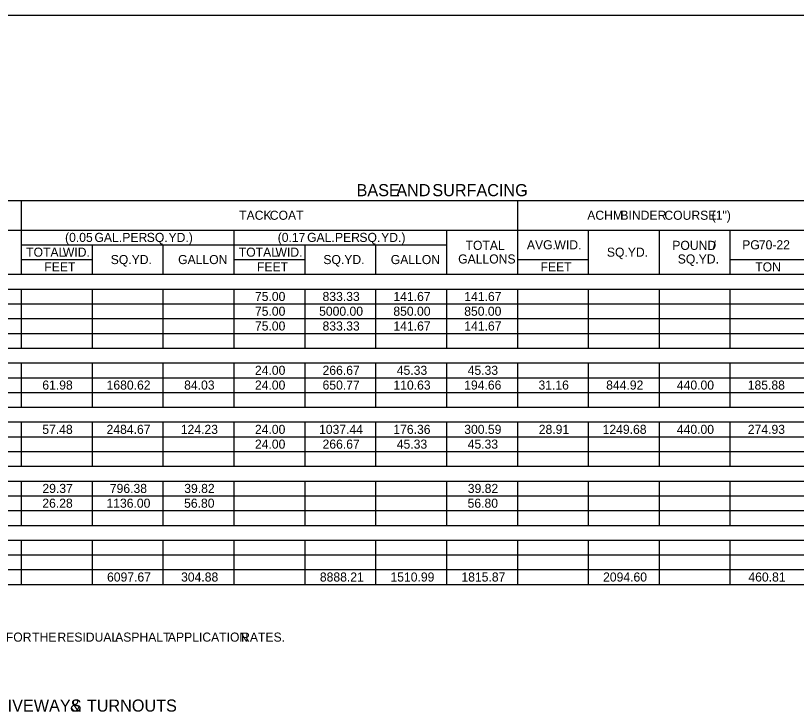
# Model space of a CAD drawing. Extents: x 3289 to 10164, y -1238 to -188.
# Drawn here: x 6334 to 6849, y -648 to -188 of the extents above; entities that cross this region are included whole.
import ezdxf

# ---------------------------------------------------------------- set-up
doc = ezdxf.new("R2010")
doc.units = 0
for name, color, linetype in [('Default', 7, 'Continuous'), ('DSN_DRFT_Named-Boundary', 7, 'Continuous'), ('DSN_QNTY_Annotation', 7, 'Continuous')]:
    doc.layers.add(name, color=color, linetype=linetype)

msp = doc.modelspace()

# ---------------------------------------------------------------- linework, layer by layer
at = {"layer": 'DSN_DRFT_Named-Boundary'}
msp.add_lwpolyline([(5913.57, -1237.74), (7538.57, -1237.74), (7538.57, -187.74), (5913.57, -187.74)], close=True, dxfattribs=at)
at = {"layer": 'DSN_QNTY_Annotation'}
for p, q in [((5941.78, -309.81), (7279.48, -309.81)), ((6337.63, -358.56), (6337.63, -309.81)), ((6665.23, -358.56), (6665.23, -309.81)), ((6244.03, -329.31), (7279.48, -329.31)), ((6478.03, -358.56), (6478.03, -329.31)), ((6618.43, -358.56), (6618.43, -329.31)), ((6712.03, -358.56), (6712.03, -329.31)), ((6758.83, -358.56), (6758.83, -329.31)), ((6805.63, -358.56), (6805.63, -329.31)), ((6337.63, -339.06), (6618.43, -339.06)), ((6384.43, -358.56), (6384.43, -339.06)), ((6431.23, -358.56), (6431.23, -339.06)), ((6524.83, -358.56), (6524.83, -339.06)), ((6571.63, -358.56), (6571.63, -339.06)), ((6337.63, -348.81), (6384.43, -348.81)), ((6384.43, -358.56), (6384.43, -348.81)), ((6478.03, -348.81), (6524.83, -348.81)), ((6524.83, -358.56), (6524.83, -348.81)), ((6665.23, -348.81), (6712.03, -348.81)), ((6712.03, -358.56), (6712.03, -348.81)), ((6805.63, -348.81), (6899.23, -348.81)), ((5941.78, -358.56), (7279.48, -358.56)), ((6244.03, -358.56), (6384.43, -358.56)), ((6384.43, -358.56), (6524.83, -358.56)), ((6524.83, -358.56), (6571.63, -358.56)), ((6571.63, -358.56), (6712.03, -358.56)), ((6712.03, -358.56), (6899.23, -358.56)), ((5941.78, -368.31), (7279.48, -368.31)), ((6337.63, -407.31), (6337.63, -368.31)), ((6337.63, -407.31), (6337.63, -368.31)), ((6384.43, -407.31), (6384.43, -368.31)), ((6384.43, -407.31), (6384.43, -368.31)), ((6431.23, -407.31), (6431.23, -368.31)), ((6431.23, -407.31), (6431.23, -368.31)), ((6478.03, -407.31), (6478.03, -368.31)), ((6478.03, -407.31), (6478.03, -368.31)), ((6524.83, -407.31), (6524.83, -368.31)), ((6524.83, -407.31), (6524.83, -368.31)), ((6571.63, -407.31), (6571.63, -368.31)), ((6571.63, -407.31), (6571.63, -368.31)), ((6618.43, -407.31), (6618.43, -368.31)), ((6618.43, -407.31), (6618.43, -368.31)), ((6665.23, -407.31), (6665.23, -368.31)), ((6665.23, -407.31), (6665.23, -368.31)), ((6712.03, -407.31), (6712.03, -368.31)), ((6712.03, -407.31), (6712.03, -368.31)), ((6758.83, -407.31), (6758.83, -368.31)), ((6758.83, -407.31), (6758.83, -368.31)), ((6805.63, -407.31), (6805.63, -368.31)), ((6805.63, -407.31), (6805.63, -368.31)), ((5941.78, -378.06), (7279.48, -378.06)), ((5941.78, -387.81), (7279.48, -387.81)), ((5941.78, -397.56), (7279.48, -397.56)), ((5941.78, -407.31), (6384.43, -407.31)), ((5941.78, -407.31), (7279.48, -407.31)), ((6384.43, -407.31), (6478.03, -407.31)), ((6478.03, -407.31), (6524.83, -407.31)), ((6524.83, -407.31), (6665.23, -407.31)), ((6665.23, -407.31), (7086.43, -407.31)), ((5941.78, -417.06), (7279.48, -417.06)), ((6337.63, -446.31), (6337.63, -417.06)), ((6337.63, -446.31), (6337.63, -417.06)), ((6384.43, -446.31), (6384.43, -417.06)), ((6384.43, -446.31), (6384.43, -417.06)), ((6431.23, -446.31), (6431.23, -417.06)), ((6431.23, -446.31), (6431.23, -417.06)), ((6478.03, -446.31), (6478.03, -417.06)), ((6478.03, -446.31), (6478.03, -417.06)), ((6524.83, -446.31), (6524.83, -417.06)), ((6524.83, -446.31), (6524.83, -417.06)), ((6571.63, -446.31), (6571.63, -417.06)), ((6571.63, -446.31), (6571.63, -417.06)), ((6618.43, -446.31), (6618.43, -417.06)), ((6618.43, -446.31), (6618.43, -417.06)), ((6665.23, -446.31), (6665.23, -417.06)), ((6665.23, -446.31), (6665.23, -417.06)), ((6712.03, -446.31), (6712.03, -417.06)), ((6712.03, -446.31), (6712.03, -417.06)), ((6758.83, -446.31), (6758.83, -417.06)), ((6758.83, -446.31), (6758.83, -417.06)), ((6805.63, -446.31), (6805.63, -417.06)), ((6805.63, -446.31), (6805.63, -417.06)), ((5941.78, -426.81), (7279.48, -426.81)), ((5941.78, -436.56), (7279.48, -436.56)), ((5941.78, -446.31), (6384.43, -446.31)), ((5941.78, -446.31), (7279.48, -446.31)), ((6384.43, -446.31), (6478.03, -446.31)), ((6478.03, -446.31), (6524.83, -446.31)), ((6524.83, -446.31), (6665.23, -446.31)), ((6665.23, -446.31), (7086.43, -446.31)), ((5941.78, -456.06), (7279.48, -456.06)), ((6337.63, -485.31), (6337.63, -456.06)), ((6337.63, -485.31), (6337.63, -456.06)), ((6384.43, -485.31), (6384.43, -456.06)), ((6384.43, -485.31), (6384.43, -456.06)), ((6431.23, -485.31), (6431.23, -456.06)), ((6431.23, -485.31), (6431.23, -456.06)), ((6478.03, -485.31), (6478.03, -456.06)), ((6478.03, -485.31), (6478.03, -456.06)), ((6524.83, -485.31), (6524.83, -456.06)), ((6524.83, -485.31), (6524.83, -456.06)), ((6571.63, -485.31), (6571.63, -456.06)), ((6571.63, -485.31), (6571.63, -456.06)), ((6618.43, -485.31), (6618.43, -456.06)), ((6618.43, -485.31), (6618.43, -456.06)), ((6665.23, -485.31), (6665.23, -456.06)), ((6665.23, -485.31), (6665.23, -456.06)), ((6712.03, -485.31), (6712.03, -456.06)), ((6712.03, -485.31), (6712.03, -456.06)), ((6758.83, -485.31), (6758.83, -456.06)), ((6758.83, -485.31), (6758.83, -456.06)), ((6805.63, -485.31), (6805.63, -456.06)), ((6805.63, -485.31), (6805.63, -456.06)), ((5941.78, -465.81), (7279.48, -465.81)), ((5941.78, -475.56), (7279.48, -475.56)), ((5941.78, -485.31), (6384.43, -485.31)), ((5941.78, -485.31), (7279.48, -485.31)), ((6384.43, -485.31), (6478.03, -485.31)), ((6478.03, -485.31), (6524.83, -485.31)), ((6524.83, -485.31), (6665.23, -485.31)), ((6665.23, -485.31), (7086.43, -485.31)), ((5941.78, -495.06), (7279.48, -495.06)), ((6337.63, -524.31), (6337.63, -495.06)), ((6337.63, -524.31), (6337.63, -495.06)), ((6384.43, -524.31), (6384.43, -495.06)), ((6384.43, -524.31), (6384.43, -495.06)), ((6431.23, -524.31), (6431.23, -495.06)), ((6431.23, -524.31), (6431.23, -495.06)), ((6478.03, -524.31), (6478.03, -495.06)), ((6478.03, -524.31), (6478.03, -495.06)), ((6524.83, -524.31), (6524.83, -495.06)), ((6524.83, -524.31), (6524.83, -495.06)), ((6571.63, -524.31), (6571.63, -495.06)), ((6571.63, -524.31), (6571.63, -495.06)), ((6618.43, -524.31), (6618.43, -495.06)), ((6618.43, -524.31), (6618.43, -495.06)), ((6665.23, -524.31), (6665.23, -495.06)), ((6665.23, -524.31), (6665.23, -495.06)), ((6712.03, -524.31), (6712.03, -495.06)), ((6712.03, -524.31), (6712.03, -495.06)), ((6758.83, -524.31), (6758.83, -495.06)), ((6758.83, -524.31), (6758.83, -495.06)), ((6805.63, -524.31), (6805.63, -495.06)), ((6805.63, -524.31), (6805.63, -495.06)), ((5941.78, -504.81), (7279.48, -504.81)), ((5941.78, -514.56), (7279.48, -514.56)), ((5941.78, -524.31), (6337.63, -524.31)), ((5941.78, -524.31), (7279.48, -524.31)), ((6337.63, -524.31), (6618.43, -524.31)), ((6618.43, -524.31), (7086.43, -524.31)), ((5941.78, -534.06), (7279.48, -534.06)), ((6337.63, -563.31), (6337.63, -534.06)), ((6337.63, -563.31), (6337.63, -534.06)), ((6384.43, -563.31), (6384.43, -534.06)), ((6384.43, -563.31), (6384.43, -534.06)), ((6431.23, -553.56), (6431.23, -534.06)), ((6431.23, -563.31), (6431.23, -534.06)), ((6478.03, -553.56), (6478.03, -534.06)), ((6478.03, -563.31), (6478.03, -534.06)), ((6524.83, -563.31), (6524.83, -534.06)), ((6524.83, -563.31), (6524.83, -534.06)), ((6571.63, -553.56), (6571.63, -534.06)), ((6571.63, -563.31), (6571.63, -534.06)), ((6618.43, -553.56), (6618.43, -534.06)), ((6618.43, -563.31), (6618.43, -534.06)), ((6665.23, -563.31), (6665.23, -534.06)), ((6665.23, -563.31), (6665.23, -534.06)), ((6712.03, -563.31), (6712.03, -534.06)), ((6712.03, -563.31), (6712.03, -534.06)), ((6758.83, -563.31), (6758.83, -534.06)), ((6758.83, -563.31), (6758.83, -534.06)), ((6805.63, -563.31), (6805.63, -534.06)), ((6805.63, -563.31), (6805.63, -534.06)), ((5941.78, -543.81), (7279.48, -543.81)), ((5941.78, -553.56), (7279.48, -553.56)), ((5941.78, -563.31), (7279.48, -563.31))]:
    msp.add_line(p, q, dxfattribs=at)

# ---------------------------------------------------------------- texts
at = {"layer": 'Default'}
for s, height, p in [('BASE', 8, (6558.85, -306.98)), (' AND', 8, (6582.12, -306.98)), (' SURFACING', 8, (6605.91, -306.98)), ('TACK', 6, (6481.34, -322.56)), (' COAT', 6, (6499.33, -322.56)), ('ACHM', 6, (6711.17, -322.56)), (' BINDER', 6, (6730.83, -322.56)), (' COURSE', 6, (6759.86, -322.56)), (' (1")', 6, (6791.1, -322.56)), ('(0.05', 6, (6366.37, -337.18)), (' GAL.', 6, (6383.53, -337.18)), (' PER', 6, (6401.94, -337.18)), (' SQ.', 6, (6418.09, -337.18)), (' YD.)', 6, (6432.46, -337.18)), ('(0.17', 6, (6506.77, -337.18)), (' GAL.', 6, (6523.94, -337.18)), (' PER', 6, (6542.35, -337.18)), (' SQ.', 6, (6558.49, -337.18)), (' YD.)', 6, (6572.86, -337.18)), ('TOTAL', 6, (6630.82, -342.43)), ('AVG.', 6, (6671.32, -342.06)), (' WID.', 6, (6687.28, -342.06)), ('POUND', 6, (6767.32, -342.43)), (' /', 6, (6791.62, -342.43)), ('PG', 6, (6813.47, -342.06)), (' 70-22', 6, (6822.25, -342.06)), ('TOTAL', 6, (6340.69, -346.93)), (' WID.', 6, (6362.7, -346.93)), ('TOTAL', 6, (6481.09, -346.93)), (' WID.', 6, (6503.1, -346.93)), ('GALLONS', 6, (6625.93, -351.43)), ('SQ.YD.', 6, (6724.13, -346.93)), ('SQ.YD.', 6, (6770.93, -351.43)), ('SQ.YD.', 6, (6396.53, -351.81)), ('GALLON', 6, (6441.03, -351.81)), ('SQ.YD.', 6, (6536.93, -351.81)), ('GALLON', 6, (6581.43, -351.81)), ('FEET', 6, (6352.71, -356.68)), ('FEET', 6, (6493.11, -356.68)), ('FEET', 6, (6680.31, -356.68)), ('TON', 6, (6822.09, -356.68)), ('75.00', 6, (6491.76, -376.18)), ('833.33', 6, (6536.39, -376.18)), ('141.67', 6, (6583.2, -376.18)), ('141.67', 6, (6630, -376.18)), ('75.00', 6, (6491.76, -385.93)), ('5000.00', 6, (6534.12, -385.93)), ('850.00', 6, (6583.14, -385.93)), ('850.00', 6, (6629.94, -385.93)), ('75.00', 6, (6491.76, -395.68)), ('833.33', 6, (6536.39, -395.68)), ('141.67', 6, (6583.2, -395.68)), ('141.67', 6, (6630, -395.68)), ('24.00', 6, (6491.76, -424.93)), ('266.67', 6, (6536.4, -424.93)), ('45.33', 6, (6585.41, -424.93)), ('45.33', 6, (6632.21, -424.93)), ('61.98', 6, (6351.36, -434.68)), ('1680.62', 6, (6393.83, -434.68)), ('84.03', 6, (6445.01, -434.68)), ('24.00', 6, (6491.76, -434.68)), ('650.77', 6, (6536.4, -434.68)), ('110.63', 6, (6583.19, -434.68)), ('194.66', 6, (6629.93, -434.68)), ('31.16', 6, (6678.95, -434.68)), ('844.92', 6, (6723.66, -434.68)), ('440.00', 6, (6770.34, -434.68)), ('185.88', 6, (6817.14, -434.68)), ('57.48', 6, (6351.36, -463.93)), ('2484.67', 6, (6393.78, -463.93)), ('124.23', 6, (6442.79, -463.93)), ('24.00', 6, (6491.76, -463.93)), ('1037.44', 6, (6534.08, -463.93)), ('176.36', 6, (6583.13, -463.93)), ('300.59', 6, (6629.95, -463.93)), ('28.91', 6, (6679.16, -463.93)), ('1249.68', 6, (6721.32, -463.93)), ('440.00', 6, (6770.34, -463.93)), ('274.93', 6, (6817.19, -463.93)), ('24.00', 6, (6491.76, -473.68)), ('266.67', 6, (6536.4, -473.68)), ('45.33', 6, (6585.41, -473.68)), ('45.33', 6, (6632.21, -473.68)), ('29.37', 6, (6351.42, -502.93)), ('796.38', 6, (6395.94, -502.93)), ('39.82', 6, (6445.08, -502.93)), ('39.82', 6, (6632.28, -502.93)), ('26.28', 6, (6351.36, -512.68)), ('1136.00', 6, (6393.72, -512.68)), ('56.80', 6, (6444.96, -512.68)), ('56.80', 6, (6632.16, -512.68)), ('6097.67', 6, (6394.09, -561.43)), ('304.88', 6, (6442.99, -561.43)), ('8888.21', 6, (6534.62, -561.43)), ('1510.99', 6, (6581.23, -561.43)), ('1815.87', 6, (6628.09, -561.43)), ('2094.60', 6, (6721.62, -561.43)), ('460.81', 6, (6817.58, -561.43)), (' FOR', 6, (6325.06, -601.11)), (' THE', 6, (6342.4, -601.11)), (' RESIDUAL', 6, (6359.11, -601.11)), (' ASPHALT', 6, (6397.2, -601.11)), (' APPLICATION', 6, (6432.04, -601.11)), (' RATES.', 6, (6480.41, -601.11)), ('DRIVEWAYS', 8, (6313.03, -647.31)), (' TURNOUTS', 8, (6377.79, -647.31)), (' &', 8, (6366.78, -647.31))]:
    msp.add_text(s, height=height, dxfattribs=at).set_placement(p)

doc.saveas('drawing.dxf')
